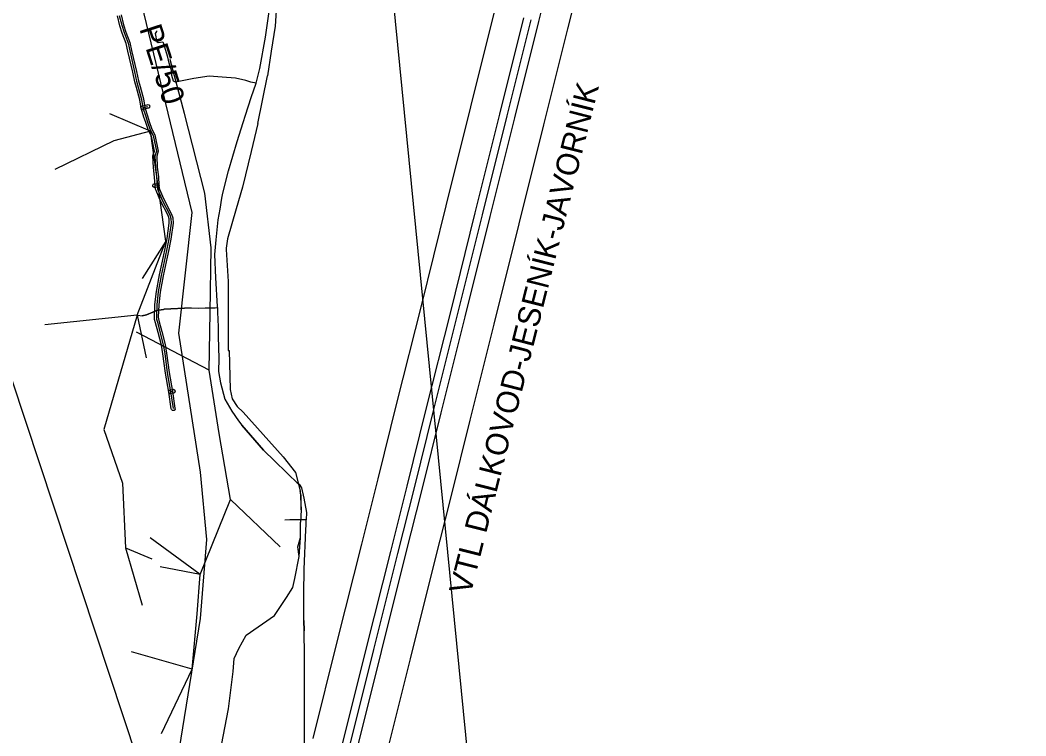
# Model space of a CAD drawing. Extents: x -555222 to -543220, y -1067119 to -1030889.
# Drawn here: x -550309 to -549771, y -1045896 to -1045513 of the extents above; entities that cross this region are included whole.
import ezdxf

# ---------------------------------------------------------------- set-up
doc = ezdxf.new("R2010")
doc.units = 0
for name, color, linetype in [('07_ELEKTRO', 7, 'Continuous'), ('07_KANALIZACE', 7, 'Continuous'), ('07_OCH_P A POPISY TI', 7, 'Continuous'), ('07_PLYNOVOD', 7, 'Continuous'), ('07_SDĚLOVACÍ', 7, 'Continuous')]:
    doc.layers.add(name, color=color, linetype=linetype)

msp = doc.modelspace()

# ---------------------------------------------------------------- linework, layer by layer
at = {"layer": '07_ELEKTRO'}
for p, q in [((-550221.19, -1045563), (-550228.91, -1045534.21)), ((-550210.21, -1045605.68), (-550221.19, -1045563)), ((-550206.87, -1045634.78), (-550210.21, -1045605.68)), ((-550207.52, -1045669.44), (-550206.87, -1045634.78)), ((-550207.9, -1045700.25), (-550207.52, -1045669.44)), ((-550207.9, -1045700.25), (-550246.79, -1045679.97)), ((-550202.56, -1045734.01), (-550207.9, -1045700.25)), ((-550196.53, -1045769.3), (-550202.56, -1045734.01)), ((-550212.81, -1045809.41), (-550196.53, -1045769.3)), ((-550196.53, -1045769.3), (-550169.99, -1045794.57)), ((-550212.81, -1045809.41), (-550239.57, -1045789.83)), ((-550212.81, -1045809.41), (-550234.26, -1045805.35)), ((-550214.47, -1045830.48), (-550212.81, -1045809.41)), ((-550217.15, -1045860), (-550214.47, -1045830.48)), ((-550217.15, -1045860), (-550249.48, -1045850.68)), ((-550233.42, -1045894.29), (-550217.15, -1045860))]:
    msp.add_line(p, q, dxfattribs=at)
at = {"layer": '07_KANALIZACE'}
msp.add_lwpolyline([(-550167.68, -1046293.63), (-550196.35, -1046241.61), (-550201.79, -1046185.91), (-550213.16, -1046120.35), (-550222.33, -1046089.55), (-550227.34, -1046017.59), (-550222.78, -1045980.5), (-550225.85, -1045914.55), (-550212.56, -1045832.85), (-550209.2, -1045790.71), (-550212.68, -1045754.66), (-550224.18, -1045680.46), (-550217.13, -1045615.96), (-550259.48, -1045440.34)], dxfattribs=at)
at = {"layer": '07_OCH_P A POPISY TI'}
for p, q in [((-550018.26, -1045459.01), (-550031.93, -1045513.89)), ((-550002.67, -1045462.66), (-550016.4, -1045517.76)), ((-550068.06, -1045559.48), (-550055.22, -1045508.08)), ((-550255.7, -1045516.13), (-550256.99, -1045510.89)), ((-550255.05, -1045510.37), (-550253.78, -1045515.59)), ((-550052.53, -1045563.35), (-550039.69, -1045511.95)), ((-550254.44, -1045520.16), (-550255.7, -1045516.13)), ((-550253.78, -1045515.59), (-550252.56, -1045519.5)), ((-550031.93, -1045513.89), (-550044.77, -1045565.29)), ((-550016.4, -1045517.76), (-550029.24, -1045569.16)), ((-550252.33, -1045525.68), (-550254.44, -1045520.16)), ((-550252.56, -1045519.5), (-550250.41, -1045525.1)), ((-550251.46, -1045529.78), (-550252.33, -1045525.68)), ((-550250.41, -1045525.1), (-550249.5, -1045529.34)), ((-550249.5, -1045529.34), (-550246.84, -1045540.55)), ((-550248.8, -1045540.99), (-550251.46, -1045529.78)), ((-550247.75, -1045546.08), (-550248.8, -1045540.99)), ((-550246.84, -1045540.55), (-550245.81, -1045545.6)), ((-550245.81, -1045545.6), (-550244.92, -1045548.62)), ((-550246.84, -1045549.16), (-550247.75, -1045546.08)), ((-550245.13, -1045555.68), (-550246.84, -1045549.16)), ((-550244.92, -1045548.62), (-550243.17, -1045555.26)), ((-550244.33, -1045560.23), (-550245.13, -1045555.68)), ((-550243.17, -1045555.26), (-550242.39, -1045559.75)), ((-550244.43, -1045559.85), (-550244.02, -1045559.13)), ((-550244.32, -1045560.25), (-550244.43, -1045559.85)), ((-550242.85, -1045564.93), (-550244.33, -1045560.23)), ((-550244.22, -1045560.65), (-550244.32, -1045560.25)), ((-550243.5, -1045561.06), (-550244.22, -1045560.65)), ((-550244.02, -1045559.13), (-550243.62, -1045559.02)), ((-550243.62, -1045559.02), (-550241.06, -1045558.32)), ((-550243.1, -1045560.96), (-550243.5, -1045561.06)), ((-550240.54, -1045560.26), (-550243.1, -1045560.96)), ((-550242.39, -1045559.75), (-550240.95, -1045564.31)), ((-550241.06, -1045558.32), (-550240.66, -1045558.22)), ((-550240.66, -1045558.22), (-550239.94, -1045558.63)), ((-550240.14, -1045560.15), (-550240.54, -1045560.26)), ((-550239.73, -1045559.43), (-550240.14, -1045560.15)), ((-550239.94, -1045558.63), (-550239.84, -1045559.03)), ((-550239.84, -1045559.03), (-550239.73, -1045559.43)), ((-550081.23, -1045612.3), (-550068.06, -1045559.48)), ((-550241.88, -1045567.89), (-550242.85, -1045564.93)), ((-550240.95, -1045564.31), (-550239.98, -1045567.27)), ((-550239.98, -1045567.27), (-550238.64, -1045571.41)), ((-550065.7, -1045616.16), (-550052.53, -1045563.35)), ((-550044.77, -1045565.29), (-550057.94, -1045618.1)), ((-550240.48, -1045572.19), (-550241.88, -1045567.89)), ((-550238.89, -1045575.18), (-550240.48, -1045572.19)), ((-550238.64, -1045571.41), (-550236.99, -1045574.5)), ((-550029.24, -1045569.16), (-550042.41, -1045621.96)), ((-550237.24, -1045583.15), (-550238.89, -1045575.18)), ((-550236.99, -1045574.5), (-550235.18, -1045583.25)), ((-550238.04, -1045585.65), (-550237.24, -1045583.15)), ((-550235.18, -1045583.25), (-550236.02, -1045585.91)), ((-550237.7, -1045591.81), (-550238.04, -1045585.65)), ((-550236.02, -1045585.91), (-550235.7, -1045591.65)), ((-550237.13, -1045597.02), (-550237.7, -1045591.81)), ((-550235.7, -1045591.65), (-550235.13, -1045596.84)), ((-550236.82, -1045601.45), (-550237.13, -1045597.02)), ((-550235.13, -1045596.84), (-550234.82, -1045601.27)), ((-550238.15, -1045601.3), (-550237.66, -1045600.64)), ((-550238.09, -1045601.71), (-550238.15, -1045601.3)), ((-550238.02, -1045602.12), (-550238.09, -1045601.71)), ((-550237.36, -1045602.61), (-550238.02, -1045602.12)), ((-550237.66, -1045600.64), (-550237.25, -1045600.57)), ((-550236.95, -1045602.55), (-550237.36, -1045602.61)), ((-550237.25, -1045600.57), (-550235.97, -1045600.37)), ((-550235.67, -1045602.35), (-550236.95, -1045602.55)), ((-550236.6, -1045603.48), (-550236.82, -1045601.45)), ((-550236.32, -1045604.19), (-550236.6, -1045603.48)), ((-550234.79, -1045608.03), (-550236.32, -1045604.19)), ((-550235.97, -1045600.37), (-550235.56, -1045600.31)), ((-550235.26, -1045602.28), (-550235.67, -1045602.35)), ((-550235.56, -1045600.31), (-550234.9, -1045600.8)), ((-550234.77, -1045601.62), (-550235.26, -1045602.28)), ((-550234.9, -1045600.8), (-550234.83, -1045601.21)), ((-550234.83, -1045601.21), (-550234.77, -1045601.62)), ((-550234.82, -1045601.27), (-550234.64, -1045603)), ((-550234.64, -1045603), (-550234.46, -1045603.45)), ((-550234.46, -1045603.45), (-550232.95, -1045607.25)), ((-550234.02, -1045609.76), (-550234.79, -1045608.03)), ((-550229.97, -1045617.62), (-550234.02, -1045609.76)), ((-550232.95, -1045607.25), (-550232.22, -1045608.9)), ((-550232.22, -1045608.9), (-550228.11, -1045616.84)), ((-550094.55, -1045665.82), (-550081.23, -1045612.3)), ((-550229.44, -1045619.25), (-550229.97, -1045617.62)), ((-550229.29, -1045621.61), (-550229.44, -1045619.25)), ((-550228.11, -1045616.84), (-550227.46, -1045618.87)), ((-550227.46, -1045618.87), (-550227.29, -1045621.69)), ((-550079.03, -1045669.71), (-550065.7, -1045616.16)), ((-550057.94, -1045618.1), (-550071.27, -1045671.65)), ((-550230.48, -1045629.9), (-550229.29, -1045621.61)), ((-550227.29, -1045621.69), (-550228.52, -1045630.24)), ((-550042.41, -1045621.96), (-550055.75, -1045675.54)), ((-550231.59, -1045635.23), (-550230.82, -1045631.54)), ((-550230.82, -1045631.54), (-550230.48, -1045629.9)), ((-550228.52, -1045630.24), (-550228.87, -1045631.95)), ((-550232.45, -1045639.37), (-550231.59, -1045635.23)), ((-550229.63, -1045635.63), (-550230.49, -1045639.79)), ((-550228.87, -1045631.95), (-550229.63, -1045635.63)), ((-550234.62, -1045649.32), (-550232.45, -1045639.37)), ((-550230.49, -1045639.79), (-550232.66, -1045649.72)), ((-550236.2, -1045658.15), (-550234.62, -1045649.32)), ((-550232.66, -1045649.72), (-550234.22, -1045658.43)), ((-550236.95, -1045665.11), (-550236.2, -1045658.15)), ((-550234.22, -1045658.43), (-550234.95, -1045665.25)), ((-550237.17, -1045671.8), (-550236.95, -1045665.11)), ((-550234.95, -1045665.25), (-550235.17, -1045671.8)), ((-550107.47, -1045717.15), (-550094.55, -1045665.82)), ((-550237.12, -1045673.04), (-550237.17, -1045671.8)), ((-550236.65, -1045674.86), (-550237.12, -1045673.04)), ((-550235.31, -1045680), (-550236.65, -1045674.86)), ((-550235.17, -1045671.8), (-550235.14, -1045672.74)), ((-550235.14, -1045672.74), (-550234.71, -1045674.36)), ((-550234.71, -1045674.36), (-550233.37, -1045679.5)), ((-550091.94, -1045721.02), (-550079.03, -1045669.71)), ((-550071.27, -1045671.65), (-550084.18, -1045722.96)), ((-550233.53, -1045686.87), (-550235.31, -1045680)), ((-550233.37, -1045679.5), (-550231.57, -1045686.45)), ((-550055.75, -1045675.54), (-550068.65, -1045726.83)), ((-550232.72, -1045691.49), (-550233.53, -1045686.87)), ((-550231.57, -1045686.45), (-550230.74, -1045691.19)), ((-550231.4, -1045701.76), (-550232.72, -1045691.49)), ((-550230.74, -1045691.19), (-550229.42, -1045701.46)), ((-550229.42, -1045701.46), (-550227.58, -1045711.56)), ((-550229.56, -1045711.88), (-550231.4, -1045701.76)), ((-550229.63, -1045711.51), (-550229.17, -1045710.82)), ((-550229.55, -1045711.92), (-550229.63, -1045711.51)), ((-550228.24, -1045720.88), (-550229.56, -1045711.88)), ((-550229.47, -1045712.32), (-550229.55, -1045711.92)), ((-550228.78, -1045712.78), (-550229.47, -1045712.32)), ((-550229.17, -1045710.82), (-550228.76, -1045710.74)), ((-550228.76, -1045710.74), (-550227.46, -1045710.48)), ((-550227.06, -1045712.44), (-550228.38, -1045712.7)), ((-550227.58, -1045711.56), (-550226.26, -1045720.58)), ((-550227.46, -1045710.48), (-550227.05, -1045710.4)), ((-550226.66, -1045712.36), (-550227.06, -1045712.44)), ((-550227.05, -1045710.4), (-550226.36, -1045710.86)), ((-550226.2, -1045711.67), (-550226.66, -1045712.36)), ((-550226.36, -1045710.86), (-550226.28, -1045711.26)), ((-550226.28, -1045711.26), (-550226.2, -1045711.67)), ((-550228.38, -1045712.7), (-550228.78, -1045712.78)), ((-550117.6, -1045758.22), (-550107.47, -1045717.15)), ((-550228.18, -1045721.28), (-550228.24, -1045720.88)), ((-550227.52, -1045721.78), (-550228.18, -1045721.28)), ((-550227.1, -1045721.72), (-550227.52, -1045721.78)), ((-550226.7, -1045721.66), (-550227.1, -1045721.72)), ((-550226.2, -1045721), (-550226.7, -1045721.66)), ((-550226.26, -1045720.58), (-550226.2, -1045721)), ((-550102.08, -1045762.1), (-550091.94, -1045721.02)), ((-550084.18, -1045722.96), (-550094.32, -1045764.04)), ((-550068.65, -1045726.83), (-550078.8, -1045767.92)), ((-550126.43, -1045793.19), (-550117.6, -1045758.22)), ((-550110.92, -1045797.1), (-550102.08, -1045762.1)), ((-550094.32, -1045764.04), (-550103.16, -1045799.06)), ((-550078.8, -1045767.92), (-550087.65, -1045802.97)), ((-550139.38, -1045844.67), (-550126.43, -1045793.19)), ((-550123.86, -1045848.55), (-550110.92, -1045797.1)), ((-550103.16, -1045799.06), (-550116.1, -1045850.49)), ((-550087.65, -1045802.97), (-550100.58, -1045854.37)), ((-550152.33, -1045896.92), (-550139.38, -1045844.67)), ((-550136.8, -1045900.76), (-550123.86, -1045848.55)), ((-550116.1, -1045850.49), (-550129.04, -1045902.68)), ((-550100.58, -1045854.37), (-550113.51, -1045906.52))]:
    msp.add_line(p, q, dxfattribs=at)
at = {"layer": '07_PLYNOVOD'}
for points in [[(-550256.02, -1045510.63), (-550254.74, -1045515.86), (-550253.5, -1045519.83), (-550251.37, -1045525.39), (-550250.48, -1045529.56), (-550247.82, -1045540.77), (-550246.78, -1045545.84), (-550245.88, -1045548.89), (-550244.15, -1045555.47), (-550243.36, -1045559.99), (-550241.9, -1045564.62), (-550240.93, -1045567.58), (-550239.56, -1045571.8), (-550237.94, -1045574.84), (-550236.21, -1045583.2), (-550237.03, -1045585.78), (-550236.7, -1045591.73), (-550236.13, -1045596.93), (-550235.82, -1045601.36), (-550235.62, -1045603.24), (-550235.39, -1045603.82), (-550233.87, -1045607.64), (-550233.12, -1045609.33), (-550229.04, -1045617.23), (-550228.45, -1045619.06), (-550228.29, -1045621.65), (-550229.5, -1045630.07), (-550229.85, -1045631.74), (-550230.61, -1045635.43), (-550231.47, -1045639.58), (-550233.64, -1045649.52), (-550235.21, -1045658.29), (-550235.95, -1045665.18), (-550236.17, -1045671.8), (-550236.13, -1045672.89), (-550235.68, -1045674.61), (-550234.34, -1045679.75), (-550232.55, -1045686.66), (-550231.73, -1045691.34), (-550230.41, -1045701.61), (-550228.57, -1045711.72), (-550227.25, -1045720.73)], [(-550256.02, -1045510.63), (-550254.74, -1045515.86), (-550253.5, -1045519.83), (-550251.37, -1045525.39), (-550250.48, -1045529.56), (-550247.82, -1045540.77), (-550246.78, -1045545.84), (-550245.88, -1045548.89), (-550244.15, -1045555.47), (-550243.36, -1045559.99), (-550241.9, -1045564.62), (-550240.93, -1045567.58), (-550239.56, -1045571.8), (-550237.94, -1045574.84), (-550236.21, -1045583.2), (-550237.03, -1045585.78), (-550236.7, -1045591.73), (-550236.13, -1045596.93), (-550235.82, -1045601.36), (-550235.62, -1045603.24), (-550235.39, -1045603.82), (-550233.87, -1045607.64), (-550233.12, -1045609.33), (-550229.04, -1045617.23), (-550228.45, -1045619.06), (-550228.29, -1045621.65), (-550229.5, -1045630.07), (-550229.85, -1045631.74), (-550230.61, -1045635.43), (-550231.47, -1045639.58), (-550233.64, -1045649.52), (-550235.21, -1045658.29), (-550235.95, -1045665.18), (-550236.17, -1045671.8), (-550236.13, -1045672.89), (-550235.68, -1045674.61), (-550234.34, -1045679.75), (-550232.55, -1045686.66), (-550231.73, -1045691.34), (-550230.41, -1045701.61), (-550228.57, -1045711.72), (-550227.25, -1045720.73)], [(-550158.41, -1046003.68), (-550145.72, -1045953.52), (-550132.92, -1045901.72), (-550119.98, -1045849.52), (-550107.04, -1045798.08), (-550098.2, -1045763.07), (-550088.06, -1045721.99), (-550075.15, -1045670.68), (-550061.82, -1045617.13), (-550048.65, -1045564.32), (-550035.81, -1045512.92)], [(-550243.36, -1045559.99), (-550240.8, -1045559.29)], [(-550235.82, -1045601.36), (-550237.1, -1045601.56)], [(-550227.26, -1045711.46), (-550228.57, -1045711.72)]]:
    msp.add_lwpolyline(points, dxfattribs=at)
at = {"layer": '07_SDĚLOVACÍ'}
for p, q in [((-555221.67, -1030889), (-543220.07, -1067118.92)), ((-550531.78, -1041228.78), (-549789.42, -1048745))]:
    msp.add_line(p, q, dxfattribs=at)
for points in [[(-550182.9, -1045546.78), (-550180.88, -1045539.02), (-550177.94, -1045522.19), (-550175.68, -1045507.28), (-550174.17, -1045490.27), (-550172.88, -1045477.8), (-550172.57, -1045476.45), (-550172.62, -1045470.4), (-550173.07, -1045468.43), (-550174.28, -1045465.49), (-550174.93, -1045463.99)], [(-550171.49, -1045496.72), (-550172.74, -1045516.42), (-550174.79, -1045529.71), (-550176.8, -1045542.82)], [(-550228.2, -1045539.85), (-550229.3, -1045536.22), (-550230.04, -1045532.98), (-550232.33, -1045525.36), (-550232.79, -1045524.96), (-550235.26, -1045525.32), (-550235.75, -1045524.96), (-550236.71, -1045520.21), (-550236.02, -1045519.22), (-550235.91, -1045518.9)], [(-550228.2, -1045539.85), (-550227.84, -1045539.78)], [(-550182.9, -1045546.78), (-550185.75, -1045546.38), (-550188.42, -1045545.44), (-550193.99, -1045544.1), (-550201.09, -1045543.67), (-550208.07, -1045543.16), (-550216.22, -1045544.28), (-550225.95, -1045546.23), (-550227.04, -1045545.72), (-550227.86, -1045542.7), (-550228.2, -1045539.85)], [(-550181.98, -1045568.38), (-550176.8, -1045542.82)], [(-550189.76, -1045567.82), (-550188.51, -1045563.96), (-550185.47, -1045554.46), (-550182.9, -1045546.78)], [(-550239.32, -1045572.44), (-550261.03, -1045563.26)], [(-550239.32, -1045572.44), (-550258.96, -1045577.73), (-550290.4, -1045592.89)], [(-550231.19, -1045631.17), (-550239.32, -1045572.44)], [(-550203.59, -1045666.2), (-550204.48, -1045650.92), (-550204.99, -1045638.43), (-550204.81, -1045636.46), (-550204.27, -1045630.57), (-550203.09, -1045619.82), (-550202.13, -1045614.19), (-550201.14, -1045608.31), (-550200.69, -1045605.69), (-550197.6, -1045593.69), (-550193.08, -1045578.06), (-550189.76, -1045567.82)], [(-550181.98, -1045568.38), (-550185.55, -1045583.28), (-550190.15, -1045602.33), (-550193.48, -1045613.91), (-550198.19, -1045629.96), (-550198.84, -1045635.06)], [(-550203.09, -1045619.82), (-550202.13, -1045614.19), (-550201.14, -1045608.31)], [(-550246.51, -1045670.75), (-550231.19, -1045631.17)], [(-550231.19, -1045631.17), (-550243.76, -1045651.13)], [(-550204.99, -1045638.43), (-550204.81, -1045636.46)], [(-550198.84, -1045635.06), (-550198.92, -1045635.65), (-550197.8, -1045652.88), (-550197.85, -1045663.65), (-550197.79, -1045689.6), (-550197.3, -1045689.7), (-550196.79, -1045710.51), (-550195.68, -1045715.45), (-550193.1, -1045719.56), (-550189.85, -1045722.65), (-550168.35, -1045746.42), (-550161.87, -1045754.78), (-550159.35, -1045764.72)], [(-550246.51, -1045670.75), (-550246.05, -1045670.8), (-550243.88, -1045671.2), (-550241.51, -1045670.68), (-550238.14, -1045669.22), (-550236.07, -1045668.39), (-550232.47, -1045667.78), (-550231.99, -1045667.53), (-550217.53, -1045666.95), (-550213.73, -1045666.98), (-550210.14, -1045666.9), (-550204.85, -1045666.84), (-550203.56, -1045666.69)], [(-550217.53, -1045666.95), (-550231.99, -1045667.53), (-550232.47, -1045667.78), (-550236.07, -1045668.39), (-550238.14, -1045669.22), (-550241.51, -1045670.68), (-550243.88, -1045671.2)], [(-550203.56, -1045666.69), (-550203.59, -1045666.2)], [(-550203.56, -1045666.69), (-550203.46, -1045669.23)], [(-550203.46, -1045669.23), (-550203.15, -1045677.04), (-550203.18, -1045677.31), (-550203.1, -1045682.26), (-550202.89, -1045693.94), (-550202.97, -1045700.85), (-550201.98, -1045707.03), (-550199.59, -1045715.65), (-550195.94, -1045722.18), (-550192.32, -1045727.26), (-550190.57, -1045729.57), (-550178.87, -1045742.88), (-550172.85, -1045748.8), (-550166.65, -1045754.89), (-550165.8, -1045755.84), (-550160.92, -1045760.37), (-550159.94, -1045761.1), (-550158.68, -1045763.11), (-550157.38, -1045768.56), (-550155.99, -1045776.19), (-550156.07, -1045780.23)], [(-550246.51, -1045670.75), (-550295.86, -1045675.9)], [(-550246.51, -1045670.75), (-550264.29, -1045731.87), (-550254.37, -1045760.54), (-550252.64, -1045795.11)], [(-550246.51, -1045670.75), (-550241.63, -1045693.63)], [(-550178.87, -1045742.88), (-550190.57, -1045729.57)], [(-550166.65, -1045754.89), (-550172.85, -1045748.8)], [(-550160.92, -1045760.37), (-550159.94, -1045761.1)], [(-550159.35, -1045764.72), (-550158.83, -1045774.73)], [(-550158.88, -1045767.14), (-550159.35, -1045764.72)], [(-550158.83, -1045774.73), (-550158.88, -1045767.14)], [(-550158.83, -1045774.73), (-550159.08, -1045781.42)], [(-550156.07, -1045780.23), (-550157.82, -1045780.23), (-550159.71, -1045780.22), (-550161.32, -1045780.22), (-550164.92, -1045780.24), (-550167.61, -1045780.31)], [(-550157.82, -1045780.23), (-550159.71, -1045780.22)], [(-550159.11, -1045789.59), (-550159.08, -1045781.42)], [(-550156.23, -1045785.43), (-550156.13, -1045782.91), (-550156.07, -1045780.23)], [(-550157.24, -1045841.12), (-550157.28, -1045839.45), (-550157.45, -1045833.9), (-550157.42, -1045819.52), (-550157.21, -1045806.49), (-550156.23, -1045785.43)], [(-550160.5, -1045794.63), (-550159.11, -1045789.59)], [(-550159.88, -1045799.82), (-550159.11, -1045789.59)], [(-550252.64, -1045795.11), (-550243.84, -1045825.78)], [(-550252.64, -1045795.11), (-550238.62, -1045800.97)], [(-550159.88, -1045799.82), (-550160.5, -1045794.63)], [(-550200.54, -1045995.61), (-550200.9, -1045988.02), (-550202.51, -1045967.27), (-550204.08, -1045946.29), (-550204.95, -1045926.76), (-550204.92, -1045917.97), (-550204.74, -1045913.13), (-550201.42, -1045900.56), (-550197.66, -1045881.1), (-550195.11, -1045861.22), (-550194.56, -1045854.22), (-550192.13, -1045848.96), (-550188.2, -1045841.86), (-550172.99, -1045831.21), (-550166.7, -1045821.67), (-550163.32, -1045816.39), (-550162.13, -1045811.47), (-550159.88, -1045799.82)], [(-550157.45, -1045833.9), (-550157.28, -1045839.45)], [(-550157.22, -1045841.7), (-550157.24, -1045841.12)], [(-550166.44, -1046058.71), (-550165.8, -1046056.56), (-550164.92, -1046053.35), (-550161.44, -1046043.65), (-550159.76, -1046038.07), (-550158.99, -1046033.25), (-550158.54, -1046029.74), (-550157.94, -1046009.68), (-550157.65, -1045991.81), (-550157.37, -1045972.25), (-550157.18, -1045950.01), (-550157.12, -1045929.18), (-550157.04, -1045912.47), (-550157.07, -1045896.16), (-550157, -1045876.93), (-550156.99, -1045850.72), (-550157.22, -1045841.7)]]:
    msp.add_lwpolyline(points, dxfattribs=at)

# ---------------------------------------------------------------- texts
at = {"layer": '07_OCH_P A POPISY TI'}
for s, rotation, p in [('PE/50', 287.8637, (-550245.42, -1045517.67)), ('VTL DÁLKOVOD-JESENÍK-JAVORNÍK', 75.8291, (-550068.26, -1045820.72))]:
    msp.add_text(s, height=12, rotation=rotation, dxfattribs=at).set_placement(p)

doc.saveas('drawing.dxf')
